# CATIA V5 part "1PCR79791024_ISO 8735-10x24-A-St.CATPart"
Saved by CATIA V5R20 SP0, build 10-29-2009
Part number: 1PCR79791024_ISO 8735-10x24-A-St
Revision: ANY
Definition: UNKNOWN
Nomenclature: 1PCR79791024_ISO 8735-10x24-A-St
Source: Unknown
Bounding box of the stored display mesh (mm): x 0 to 24, y -5 to 5, z -5 to 5
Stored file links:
  C:\Users\Utente\Desktop\IO LAVORO\3D X SITO CF\CUMSA\3D files RC\RC 205010\1PCR79791024_ISO 8735-10x24-A-St.CATPart
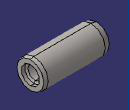
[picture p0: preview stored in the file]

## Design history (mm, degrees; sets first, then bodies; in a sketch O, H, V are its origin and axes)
Body1 "TypeA" (main body)
  Solid1: solid without history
